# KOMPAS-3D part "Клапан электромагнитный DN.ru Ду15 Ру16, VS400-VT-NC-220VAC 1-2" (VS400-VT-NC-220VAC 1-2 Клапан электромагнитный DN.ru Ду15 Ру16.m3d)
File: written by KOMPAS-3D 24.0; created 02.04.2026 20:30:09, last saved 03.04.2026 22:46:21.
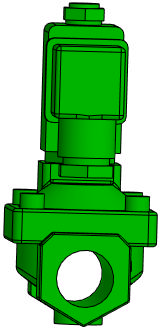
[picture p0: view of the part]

Document properties: Автор: artio; Полное имя файла: C:\Users\artio\OneDrive\Рабочий стол\Клапан электромагнитный DN.ru\VS400-VT-NC\VS400-VT-NC-220VAC 1-2 Клапан электромагнитный DN.ru Ду15 Ру16.m3d

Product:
- Body: Тело 1  | qty 1
    Масса: 1.030062
- Part/product: Клапан электромагнитный DN.ru Ду15 Ру16  | designation VS400-VT-NC-220VAC 1-2
    Масса: 0.759
    Раздел спецификации: Прочие изделия
    Примечание: D130-04698
    additional columns: ef56311e-7521-43dc-8291-0e6108b3d81d; VS400-ET-NC-220VAC 1-2; artio; c; Шероховатость не задана; Да

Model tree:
1. Операция без истории:1

Expressions: VS400-VT-NC-220VAC 1-2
